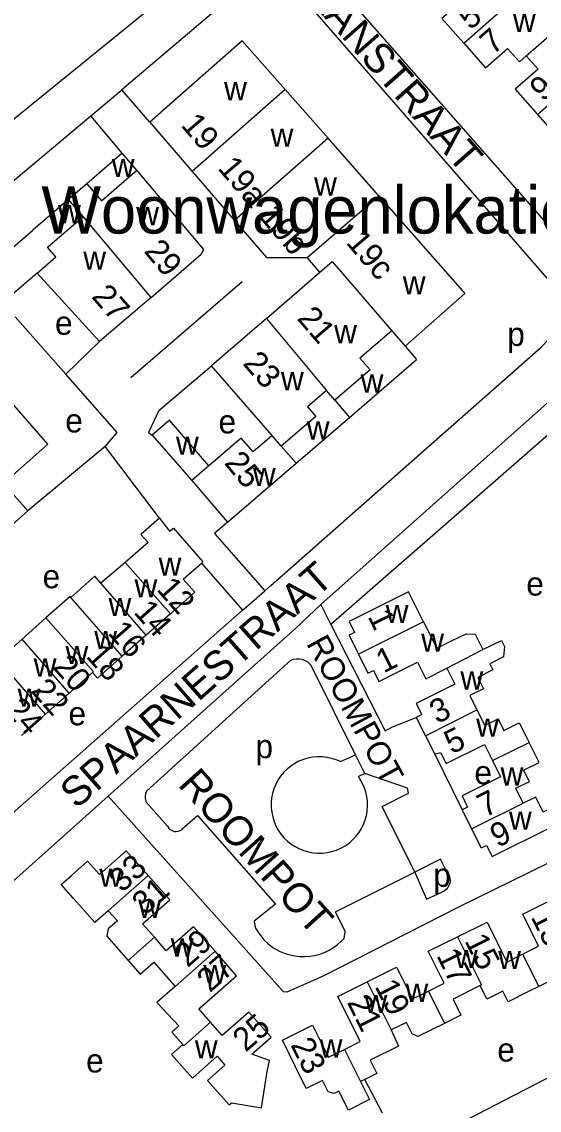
# Model space of a CAD drawing. Extents: x 156721 to 158827, y 386657 to 388950.
# Drawn here: x 157555.9 to 157643.5, y 387710.2 to 387894.5 of the extents above; entities that cross this region are included whole.
import ezdxf

# ---------------------------------------------------------------- set-up
doc = ezdxf.new("R2010")
doc.units = 0
for name, color, linetype in [('BLT_Basislijn', 7, 'Continuous'), ('BLT_Bebouwing', 7, 'Continuous'), ('BLT_Centroide', 7, 'Continuous'), ('BLT_Huisnummer', 7, 'Continuous'), ('BLT_Huisnummer_ tussenligend', 7, 'Continuous'), ('BLT_Onderverdeling_panden', 7, 'Continuous'), ('BLT_Straatnaam', 7, 'Continuous'), ('BLT_Straatnaam_verkleind', 7, 'Continuous'), ('BLT_Terrein_beschrifting', 7, 'Continuous')]:
    doc.layers.add(name, color=color, linetype=linetype)

msp = doc.modelspace()

# ---------------------------------------------------------------- linework, layer by layer
at = {"layer": 'BLT_Basislijn'}
for p, q in [((157608.95, 387901.04), (157671.09, 387830.36)), ((157567.63, 387878.57), (157572.88, 387882.96)), ((157577.61, 387877.48), (157572.88, 387882.96)), ((157600.49, 387883.02), (157584.78, 387869.14)), ((157607.78, 387874.78), (157600.49, 387883.02)), ((157542.05, 387857.12), (157567.63, 387878.57)), ((157577.61, 387877.48), (157584.78, 387869.14)), ((157607.78, 387874.78), (157591.94, 387860.83)), ((157616.37, 387865.02), (157607.78, 387874.78)), ((157584.78, 387869.14), (157591.94, 387860.83)), ((157566.92, 387867.09), (157563.84, 387864.43)), ((157604.25, 387854.58), (157616.37, 387865.02)), ((157577.81, 387847.83), (157566.33, 387861.54)), ((157605.64, 387852.96), (157604.25, 387854.58)), ((157597.38, 387844.26), (157606.38, 387852.11)), ((157606.38, 387852.11), (157605.64, 387852.96)), ((157574.39, 387834.3), (157593.21, 387850.54)), ((157577.81, 387847.83), (157569.11, 387840.36)), ((157563.41, 387834.83), (157554.84, 387844.52)), ((157597.38, 387844.26), (157588.03, 387836.25)), ((157597.38, 387844.26), (157607.51, 387832.05)), ((157563.41, 387834.83), (157569.11, 387840.36)), ((157579.14, 387828.71), (157588.03, 387836.25)), ((157598.32, 387824.48), (157588.03, 387836.25)), ((157572.07, 387824.98), (157563.41, 387834.83)), ((157652.39, 387831.01), (157630.79, 387812.14)), ((157579.14, 387828.71), (157577.39, 387824.98)), ((157570.05, 387822.57), (157572.07, 387824.98)), ((157577.39, 387824.98), (157577.99, 387824.5)), ((157570.05, 387822.57), (157556.97, 387811.71)), ((157579.26, 387810.48), (157570.05, 387822.57)), ((157630.79, 387812.14), (157608.27, 387792.47)), ((157586.35, 387802.83), (157593.29, 387794.87)), ((157597.06, 387798.16), (157598.1, 387799.07)), ((157593.89, 387795.39), (157597.06, 387798.16)), ((157549.68, 387756.41), (157593.29, 387794.87)), ((157593.29, 387794.87), (157593.89, 387795.39)), ((157602.33, 387791.84), (157606.55, 387795.84)), ((157606.55, 387795.84), (157608.27, 387792.47)), ((157602.33, 387791.84), (157574.9, 387767.32)), ((157601.5, 387786.43), (157577.05, 387764.23)), ((157612.44, 387770.42), (157604.92, 387785.5)), ((157609.88, 387769.25), (157612.44, 387770.42)), ((157614.02, 387767.24), (157612.44, 387770.42)), ((157625.87, 387770.52), (157630.48, 387761.1)), ((157570.53, 387763.42), (157574.9, 387767.32)), ((157614.02, 387767.24), (157612.9, 387766.72)), ((157570.53, 387763.42), (157530.74, 387727.79)), ((157577.01, 387762.37), (157580.6, 387758.31)), ((157622.44, 387750.55), (157616.92, 387761.68)), ((157620.45, 387703.08), (157646.13, 387716.35)), ((157617, 387709.73), (157614.02, 387715.47))]:
    msp.add_line(p, q, dxfattribs=at)
for points in [[(157589.35, 387906.27), (157534.05, 387861.36), (157532.64, 387860.36)], [(157598.1, 387799.07), (157643.84, 387839.41), (157647.1, 387842.84), (157647.76, 387845.18), (157647.71, 387846.88), (157647.26, 387848.11), (157645.66, 387850.18), (157604.01, 387897.98), (157602.32, 387899.85), (157600.43, 387901.14), (157597.4, 387901.74), (157596.12, 387901.62), (157592.52, 387899.67), (157572.88, 387882.96)], [(157600.49, 387883.02), (157593.21, 387891.26), (157577.61, 387877.48)], [(157572.92, 387872.26), (157567.63, 387878.57)], [(157577.81, 387847.83), (157586.29, 387855.14), (157586.77, 387855.94), (157575.4, 387869.38)], [(157616.37, 387865.02), (157630.91, 387848.51), (157620.8, 387839.61)], [(157591.94, 387860.83), (157597.33, 387854.57), (157604.25, 387854.58)], [(157606.38, 387852.11), (157608.48, 387853.92), (157618.56, 387842.19)], [(157569.11, 387840.36), (157558.54, 387851.95)], [(157606.55, 387795.84), (157652.53, 387836.74), (157655.97, 387837.33), (157658.59, 387836.21), (157674.23, 387819.3), (157677.74, 387817.47)], [(157590.76, 387809.77), (157588.58, 387807.89), (157597.06, 387798.16)], [(157608.27, 387792.47), (157617.43, 387774.46), (157618.67, 387775.16), (157622.71, 387776.75)], [(157601.5, 387786.43), (157601.95, 387786.58), (157602.42, 387786.66), (157602.89, 387786.65), (157603.36, 387786.57), (157603.81, 387786.41), (157604.23, 387786.18), (157604.6, 387785.88), (157604.92, 387785.5)], [(157609.88, 387769.25), (157609.14, 387769.57), (157608.37, 387769.81), (157607.58, 387769.98), (157606.77, 387770.06), (157605.97, 387770.07), (157605.16, 387770), (157604.37, 387769.84), (157603.6, 387769.61), (157602.85, 387769.31), (157602.13, 387768.93), (157601.46, 387768.49), (157600.83, 387767.98), (157600.26, 387767.4), (157599.75, 387766.78), (157599.3, 387766.11), (157598.92, 387765.4), (157598.61, 387764.65), (157598.38, 387763.88), (157598.22, 387763.08), (157598.15, 387762.28), (157598.15, 387761.47), (157598.23, 387760.67), (157598.4, 387759.88), (157598.64, 387759.11), (157598.95, 387758.36), (157599.34, 387757.65), (157599.79, 387756.98), (157600.31, 387756.36), (157600.89, 387755.8), (157601.52, 387755.3), (157602.2, 387754.86), (157602.92, 387754.49), (157603.67, 387754.19), (157604.44, 387753.96), (157605.24, 387753.82), (157606.04, 387753.75), (157606.85, 387753.77), (157607.65, 387753.86), (157608.44, 387754.04), (157609.21, 387754.29), (157609.95, 387754.61), (157610.65, 387755.01), (157611.32, 387755.47), (157611.93, 387756), (157612.49, 387756.58), (157612.98, 387757.22), (157613.41, 387757.91), (157613.77, 387758.63), (157614.06, 387759.38), (157614.27, 387760.16), (157614.31, 387760.36)], [(157616.92, 387761.68), (157621.4, 387763.91), (157621.23, 387764.76), (157614.02, 387767.24)], [(157614.31, 387760.36), (157614.41, 387760.96), (157614.46, 387761.76), (157614.44, 387762.57), (157614.33, 387763.37), (157614.15, 387764.16), (157613.89, 387764.92), (157613.55, 387765.66), (157613.15, 387766.36), (157612.9, 387766.72)], [(157658.58, 387747.17), (157652.04, 387755.18), (157651.25, 387755.09), (157629.76, 387744.54), (157607.07, 387733.01), (157600.82, 387730.24), (157600.24, 387730.27), (157570.53, 387763.42)], [(157577.05, 387764.23), (157576.9, 387763.83), (157576.84, 387763.41), (157576.84, 387762.99), (157576.93, 387762.57), (157577.01, 387762.37)], [(157583.46, 387758.2), (157585.66, 387760.12), (157598.86, 387745.12), (157595.28, 387742.22), (157595.45, 387741.2)], [(157580.6, 387758.31), (157580.8, 387758.01), (157581.06, 387757.76), (157581.37, 387757.57), (157581.71, 387757.45), (157582.07, 387757.42), (157582.43, 387757.46), (157582.77, 387757.58), (157583.08, 387757.77), (157583.33, 387758.03), (157583.46, 387758.2)], [(157627.89, 387750.59), (157626.82, 387752.75), (157622.44, 387750.55)], [(157610.48, 387739.32), (157610.65, 387740.51), (157609.01, 387743.81), (157622.44, 387750.55)], [(157622.44, 387750.55), (157624.45, 387745.95), (157627.04, 387747.17)], [(157627.89, 387750.59), (157628.14, 387750.25), (157628.31, 387749.88), (157628.4, 387749.48), (157628.42, 387749.06), (157628.36, 387748.65), (157628.22, 387748.27), (157628.01, 387747.91), (157627.74, 387747.6), (157627.41, 387747.35), (157627.04, 387747.17)], [(157595.45, 387741.2), (157595.88, 387740.45), (157596.37, 387739.76), (157596.93, 387739.11), (157597.55, 387738.51), (157598.22, 387737.98), (157598.94, 387737.51), (157599.69, 387737.11), (157600.49, 387736.78), (157601.3, 387736.53), (157602.14, 387736.35), (157602.99, 387736.25), (157603.85, 387736.24), (157604.71, 387736.3), (157605.55, 387736.44), (157606.38, 387736.66), (157607.18, 387736.96), (157607.96, 387737.33), (157608.69, 387737.77), (157609.38, 387738.28), (157610.02, 387738.84), (157610.48, 387739.32)]]:
    msp.add_lwpolyline(points, dxfattribs=at)
at = {"layer": 'BLT_Bebouwing'}
for p, q in [((157572.92, 387872.26), (157566.92, 387867.09)), ((157575.4, 387869.38), (157572.92, 387872.26)), ((157563.84, 387864.43), (157557.8, 387859.23)), ((157566.33, 387861.54), (157563.84, 387864.43)), ((157618.56, 387842.19), (157620.8, 387839.61)), ((157620.8, 387839.61), (157622.77, 387837.32)), ((157611.38, 387827.52), (157622.77, 387837.32)), ((157608.91, 387830.42), (157607.51, 387832.05)), ((157602.36, 387819.75), (157611.38, 387827.52)), ((157577.99, 387824.5), (157584.73, 387816.82)), ((157599.86, 387822.68), (157598.32, 387824.48)), ((157590.76, 387809.77), (157602.36, 387819.75)), ((157552.86, 387816.36), (157556.97, 387811.71)), ((157584.73, 387816.82), (157590.76, 387809.77)), ((157556.97, 387811.71), (157549.49, 387805.09)), ((157573.42, 387802.97), (157569.34, 387799.45)), ((157581.1, 387794.29), (157576.98, 387790.66)), ((157576.98, 387790.66), (157572.95, 387787.11)), ((157567.92, 387784.34), (157563.96, 387780.83)), ((157563.96, 387780.83), (157559.93, 387777.26)), ((157559.93, 387777.26), (157555.88, 387773.67)), ((157622.71, 387776.75), (157624.29, 387773.63)), ((157624.29, 387773.63), (157625.87, 387770.52)), ((157630.48, 387761.1), (157632.08, 387757.88)), ((157614.02, 387715.47), (157613.25, 387715.09))]:
    msp.add_line(p, q, dxfattribs=at)
for points in [[(157628.77, 387900.64), (157630.79, 387898.35), (157627.04, 387895.04), (157630.73, 387890.86)], [(157630.73, 387890.86), (157634.42, 387886.68), (157638.15, 387889.97), (157640.17, 387887.69), (157641.33, 387888.72)], [(157641.33, 387888.72), (157643.31, 387886.48), (157639.46, 387883.08), (157643.24, 387878.8)], [(157643.24, 387878.8), (157647.01, 387874.53), (157650.81, 387877.89), (157652.77, 387875.67)], [(157566.92, 387867.09), (157569.4, 387864.21), (157575.4, 387869.38)], [(157558.54, 387851.95), (157561.71, 387854.69), (157560.29, 387856.34), (157566.33, 387861.54)], [(157550.68, 387853.1), (157557.8, 387859.23)], [(157558.54, 387851.95), (157554.59, 387848.55), (157550.68, 387853.1)], [(157618.56, 387842.19), (157613.17, 387837.53), (157614.91, 387835.55), (157608.91, 387830.42)], [(157552.86, 387816.36), (157560.37, 387822.98), (157548.08, 387836.97)], [(157607.51, 387832.05), (157604.32, 387829.32), (157605.71, 387827.69), (157599.86, 387822.68)], [(157587.6, 387819.3), (157580.91, 387827.03), (157577.99, 387824.5)], [(157598.32, 387824.48), (157595.09, 387821.69), (157593.06, 387824.03), (157587.6, 387819.3)], [(157579.26, 387810.48), (157576.09, 387807.71), (157577.32, 387806.34), (157573.42, 387802.97)], [(157579.26, 387810.48), (157580.94, 387808.29), (157581.63, 387808.78), (157586.6, 387803.06), (157586.35, 387802.83)], [(157581.1, 387794.29), (157585.22, 387797.92), (157583.26, 387800.13), (157586.35, 387802.83)], [(157569.34, 387799.45), (157568.29, 387800.63), (157564.26, 387797.04)], [(157564.26, 387797.04), (157564.1, 387797.22), (157560.02, 387793.58)], [(157623.95, 387792.91), (157621.41, 387798.02), (157611.33, 387793), (157612.26, 387791.11), (157611.34, 387790.67), (157612.94, 387787.43)], [(157560.02, 387793.58), (157555.99, 387789.97)], [(157623.95, 387792.91), (157626.17, 387788.44), (157628.76, 387789.73), (157631.13, 387790.91), (157632.67, 387790.85), (157633.99, 387788.21)], [(157555.99, 387789.97), (157552.01, 387786.42)], [(157633.99, 387788.21), (157637.12, 387789.77), (157637.63, 387788.75), (157637.45, 387786.97), (157635.17, 387785.83), (157635.68, 387784.8), (157633.1, 387783.51), (157634.06, 387781.58), (157631.77, 387780.44), (157632.97, 387778.04)], [(157612.94, 387787.43), (157614.53, 387784.21), (157615.44, 387784.68), (157616.37, 387782.8), (157622.91, 387786.07), (157624.31, 387783.28), (157627.89, 387785.07)], [(157572.95, 387787.11), (157568.74, 387783.4), (157567.92, 387784.34)], [(157627.89, 387785.07), (157629.24, 387782.36), (157622.7, 387779.1), (157623.62, 387777.22), (157622.71, 387776.75)], [(157632.97, 387778.04), (157634.3, 387775.36), (157636.58, 387776.49), (157637.55, 387774.55), (157640.13, 387775.84), (157641.25, 387773.6), (157641.79, 387772.51)], [(157625.87, 387770.52), (157626.81, 387770.8), (157627.76, 387768.92), (157634.23, 387772.14), (157635.59, 387769.42)], [(157640.81, 387762.23), (157639.56, 387764.75), (157641.85, 387765.89), (157640.88, 387767.83), (157643.48, 387769.12), (157641.79, 387772.51)], [(157635.59, 387769.42), (157636.95, 387766.69), (157630.47, 387763.46), (157631.36, 387761.55), (157630.48, 387761.1)], [(157647.69, 387758.89), (157646.33, 387761.78), (157644.21, 387760.72), (157642.94, 387763.26), (157640.81, 387762.23)], [(157632.08, 387757.88), (157633.69, 387754.66), (157634.59, 387755.08), (157635.57, 387753.22), (157645.64, 387758.23), (157645.78, 387757.94), (157647.69, 387758.89)], [(157565.69, 387744.95), (157564.69, 387746.09), (157562.59, 387748.47), (157564.33, 387750), (157567.08, 387752.42), (157569.09, 387750.14), (157573.63, 387754.14), (157577.34, 387749.97)], [(157578.38, 387739.51), (157576.37, 387741.79), (157580.99, 387745.86), (157577.34, 387749.97)], [(157640.71, 387736.66), (157643.4, 387737.99), (157640.73, 387743.41), (157645.7, 387745.89)], [(157570.58, 387744.01), (157568.29, 387742), (157565.69, 387744.95)], [(157570.58, 387744.01), (157572.11, 387742.28), (157570.58, 387740.93), (157570.31, 387739.7), (157571.89, 387737.91), (157573.93, 387735.59)], [(157588.65, 387737.15), (157585.01, 387741.29), (157580.39, 387737.22), (157578.38, 387739.51)], [(157629.71, 387739.62), (157634.68, 387742.1), (157638.03, 387735.33), (157640.71, 387736.66)], [(157624.75, 387730.41), (157627.43, 387731.75), (157624.73, 387737.15), (157629.71, 387739.62)], [(157649.77, 387737.73), (157644.94, 387735.33), (157646.3, 387732.6), (157643.43, 387731.17)], [(157587.87, 387725.13), (157585.89, 387727.38), (157592.29, 387733.01), (157588.65, 387737.15)], [(157573.93, 387735.59), (157575.98, 387733.27), (157578.27, 387735.29), (157581.88, 387731.2)], [(157614.4, 387732), (157619.38, 387734.47), (157622.08, 387729.08), (157624.75, 387730.41)], [(157581.88, 387731.2), (157578.82, 387728.47), (157582.53, 387724.53), (157581.32, 387723.47), (157583.18, 387721.35)], [(157610.54, 387720.54), (157613.22, 387721.88), (157609.42, 387729.52), (157614.4, 387732)], [(157633.52, 387731.33), (157628.93, 387729.04), (157630.27, 387726.33), (157627.49, 387724.94)], [(157643.43, 387731.17), (157641.82, 387730.37), (157638.28, 387728.6), (157637.38, 387730.4), (157634.66, 387729.05), (157633.52, 387731.33)], [(157583.18, 387721.35), (157581.29, 387719.68), (157584.81, 387715.68), (157589, 387719.38), (157590.31, 387717.89), (157587.36, 387715.28), (157591.02, 387711.13), (157591.45, 387711.49), (157596.52, 387710.66), (157597.46, 387716.81), (157597.85, 387718.66), (157594.9, 387719.71), (157598.17, 387722.59), (157594.38, 387726.87), (157589.84, 387722.88), (157587.87, 387725.13)], [(157627.49, 387724.94), (157622.99, 387722.71), (157622, 387723.16), (157621.03, 387725.11), (157618.46, 387723.83)], [(157613.25, 387715.09), (157614.79, 387712.04), (157611.22, 387710.27), (157609.61, 387713.49), (157608.82, 387713.09), (157607.8, 387713.37), (157606.84, 387715.3), (157604.09, 387713.93), (157602.26, 387717.61), (157600.04, 387722.08), (157605.16, 387724.63), (157607.86, 387719.21), (157610.54, 387720.54)], [(157618.46, 387723.83), (157619.68, 387721.1), (157614.92, 387718.73), (157616.04, 387716.48), (157614.02, 387715.47)]]:
    msp.add_lwpolyline(points, dxfattribs=at)
at = {"layer": 'BLT_Onderverdeling_panden'}
for p, q in [((157630.73, 387890.86), (157639.66, 387898.74)), ((157641.33, 387888.72), (157646.86, 387893.55)), ((157643.24, 387878.8), (157650.68, 387885.38)), ((157608.91, 387830.42), (157611.38, 387827.52)), ((157599.86, 387822.68), (157602.36, 387819.75)), ((157587.6, 387819.3), (157584.73, 387816.82)), ((157581.1, 387794.29), (157573.42, 387802.97)), ((157576.98, 387790.66), (157569.34, 387799.45)), ((157572.95, 387787.11), (157564.26, 387797.04)), ((157623.95, 387792.91), (157612.94, 387787.43)), ((157563.96, 387780.83), (157555.99, 387789.97)), ((157627.89, 387785.07), (157633.99, 387788.21)), ((157559.93, 387777.26), (157552.01, 387786.42)), ((157624.29, 387773.63), (157632.97, 387778.04)), ((157635.59, 387769.42), (157641.79, 387772.51)), ((157632.08, 387757.88), (157640.81, 387762.23)), ((157570.58, 387744.01), (157577.34, 387749.97)), ((157578.38, 387739.51), (157573.93, 387735.59)), ((157588.65, 387737.15), (157581.88, 387731.2)), ((157640.71, 387736.66), (157643.43, 387731.17)), ((157614.4, 387732), (157618.46, 387723.83)), ((157624.75, 387730.41), (157627.49, 387724.94)), ((157610.54, 387720.54), (157613.25, 387715.09))]:
    msp.add_line(p, q, dxfattribs=at)
for points in [[(157567.92, 387784.34), (157568.05, 387784.46), (157560.02, 387793.58)], [(157629.71, 387739.62), (157633.77, 387731.45), (157633.52, 387731.33)], [(157587.87, 387725.13), (157583.36, 387721.16), (157583.18, 387721.35)]]:
    msp.add_lwpolyline(points, dxfattribs=at)

# ---------------------------------------------------------------- texts
at = {"layer": 'BLT_Centroide'}
for s, p in [('w', (157639.07, 387892.78)), ('w', (157590.17, 387881.21)), ('w', (157598.05, 387873.33)), ('w', (157571.16, 387868.22)), ('w', (157605.41, 387865.08)), ('w', (157562.06, 387860.38)), ('w', (157575.3, 387860.05)), ('w', (157566.34, 387852.53)), ('w', (157620.42, 387848.35)), ('e', (157561.56, 387841.51)), ('w', (157608.8, 387840.08)), ('p', (157638.1, 387839.62)), ('w', (157599.8, 387832.11)), ('w', (157613.28, 387831.72)), ('e', (157563.29, 387824.98)), ('e', (157589.23, 387824.81)), ('w', (157604.16, 387823.78)), ('w', (157582.03, 387821.2)), ('w', (157595.05, 387815.91)), ('w', (157579.09, 387800.72)), ('e', (157559.46, 387798.6)), ('e', (157641.33, 387797.36)), ('w', (157575.02, 387797.06)), ('w', (157570.62, 387793.89)), ('w', (157617.53, 387792.72)), ('w', (157568.2, 387788.3)), ('w', (157623.54, 387787.84)), ('w', (157563.33, 387785.77)), ('w', (157557.95, 387783.64)), ('w', (157630.17, 387781.44)), ('w', (157555.23, 387778.56)), ('e', (157563.84, 387775.4)), ('w', (157632.84, 387773.47)), ('p', (157595.49, 387769.84)), ('e', (157632.54, 387765.42)), ('w', (157636.97, 387765.2)), ('w', (157638.39, 387757.72)), ('w', (157569.06, 387748.06)), ('p', (157625.59, 387748.07)), ('w', (157575.66, 387742.8)), ('w', (157581.15, 387736.25)), ('w', (157629.25, 387734.31)), ('w', (157636.56, 387734.14)), ('w', (157586.66, 387731.73)), ('w', (157620.88, 387728.59)), ('w', (157613.94, 387726.69)), ('w', (157585.23, 387719)), ('w', (157606.35, 387719.16)), ('e', (157636.42, 387718.48)), ('e', (157566.82, 387716.63))]:
    msp.add_text(s, height=4, dxfattribs=at).set_placement(p)
at = {"layer": 'BLT_Huisnummer'}
for s, rotation, p in [('5', 41.4374, (157631.89, 387892.97)), ('9', 41.4374, (157644.12, 387880.84)), ('19', 310.5587, (157582.73, 387876.94)), ('19a', 310.5587, (157588.99, 387869.63)), ('19b', 310.5587, (157595.98, 387861.46)), ('29', 309.9435, (157576.49, 387855.6)), ('19c', 310.5587, (157610.68, 387857.06)), ('27', 311.1864, (157567.6, 387847.9)), ('21', 310.5587, (157602.4, 387844.21)), ('23', 311.1808, (157593.21, 387836.58)), ('25', 309.8937, (157590.07, 387819.75)), ('12', 311.3922, (157578.62, 387798.35)), ('1', 296.1765, (157614.42, 387793.86)), ('16', 311.3832, (157570.37, 387790.96)), ('1', 26.5651, (157617.18, 387784.16)), ('20', 311.5348, (157561.03, 387785.17)), ('24', 311.5333, (157552.95, 387777.88)), ('5', 26.4694, (157628.71, 387770.44)), ('9', 26.4261, (157636.48, 387754.62)), ('33', 41.406, (157572.9, 387746.96)), ('29', 41.3312, (157584.01, 387734.29)), ('15', 296.5032, (157630.81, 387738.94)), ('19', 296.5032, (157615.61, 387731.23)), ('25', 41.4054, (157593.84, 387719.96)), ('23', 296.5032, (157601.36, 387721.33))]:
    msp.add_text(s, height=4, rotation=rotation, dxfattribs=at).set_placement(p)
at = {"layer": 'BLT_Huisnummer_ tussenligend'}
for s, rotation, p in [('7', 41.4374, (157635.68, 387888.76)), ('14', 311.3922, (157574.73, 387794.48)), ('18', 311.3922, (157566.67, 387787.02)), ('22', 311.3922, (157557.33, 387781.18)), ('3', 26.5651, (157626.24, 387775.57)), ('7', 26.5651, (157634.3, 387759.72)), ('31', 41.4054, (157576.8, 387743.08)), ('13', 296.5032, (157642.03, 387742.96)), ('27', 41.4054, (157587.77, 387730.04)), ('17', 296.5032, (157626.04, 387736.45)), ('21', 296.5032, (157610.92, 387728.53))]:
    msp.add_text(s, height=4, rotation=rotation, dxfattribs=at).set_placement(p)
at = {"layer": 'BLT_Straatnaam'}
for s, rotation, p in [('ZAANSTRAAT', 311.3927, (157601.3, 387901.78)), ('SPAARNESTRAAT', 41.4423, (157565.21, 387761.1)), ('ROOMPOT', 311.8721, (157582.22, 387765.27))]:
    msp.add_text(s, height=5, rotation=rotation, dxfattribs=at).set_placement(p)
at = {"layer": 'BLT_Straatnaam_verkleind'}
msp.add_text('ROOMPOT', height=4, rotation=298.5731, dxfattribs=at).set_placement((157604.01, 387789.26))
at = {"layer": 'BLT_Terrein_beschrifting'}
msp.add_text('Woonwagenlokatie', height=8, dxfattribs=at).set_placement((157559.24, 387858.65))

doc.saveas('drawing.dxf')
